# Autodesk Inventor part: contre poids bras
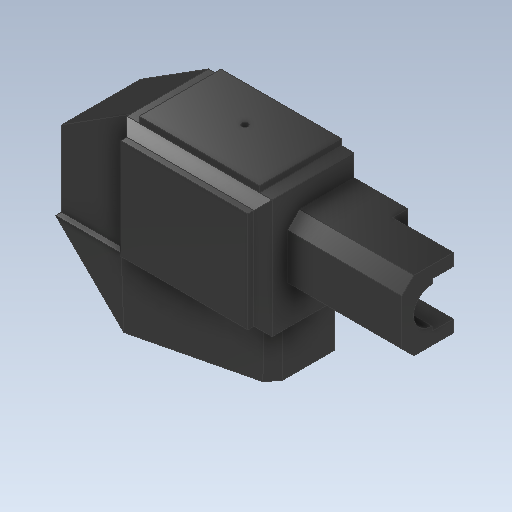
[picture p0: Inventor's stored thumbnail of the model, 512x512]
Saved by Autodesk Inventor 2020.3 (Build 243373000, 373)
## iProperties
Created: 2020-09
Part Number: contre poids bras
Material: Plastique ABS
Document SubType Name: Modeling
Designer: ficho
Density: 1.06 g/cm^3
Appearance: Lustré - Noir
Mass: 4.50875 g
Surface Area: 76.0656 cm^2
Volume: 4.25353 cm^3
Author: ficho
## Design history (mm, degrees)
sketch "Esquisse1"
  geometry: L1 (0, 0)-(146.6, 0); L2 (146.6, 0)-(146.6, -67.192); L3 (146.6, -67.192)-(0, -67.192); L4 (0, -67.192)-(0, 0); L5 (44.063, -33.051)-(55.308, -25.94); L6 (55.308, -25.94)-(79.294, -25.94); L7 (79.294, -25.94)-(79.294, -45.526); L8 (79.294, -45.526)-(76.04, -45.526); L9 (76.04, -45.526)-(76.04, -55.832); L10 (76.04, -55.832)-(55.308, -56.615); L11 (55.308, -56.615)-(44.063, -45.526); L12 (44.063, -45.526)-(44.063, -33.051); L13 (79.294, -29.495)-(98.206, -29.495); L14 (98.206, -29.495)-(98.206, -41.006); L15 (98.206, -41.006)-(79.294, -41.006); 2 further points; 1 other entity
  constraints: 22 end point, 5 perpendicular, 3 point on line, 2 horizontal, 1 parallel, 2 other
  dimensions: "d4" = 146.6 distance between parallel lines of L2 L4
  node "Image1"
extrude "Extrusion1" new body sketch "Esquisse1" distance "d6" = 15; taper "d7" = 0 deg
sketch "Esquisse2"
  geometry: L1 (79.294, -25.94)-(55.308, -25.94) reference; L2 (55.308, -25.94)-(55.308, -45.526); L3 (55.308, -45.526)-(43.978, -45.526); L4 (43.978, -45.526)-(43.978, -33.013); L5 (43.978, -33.013)-(55.308, -25.94); 1 further point
  constraints: 8 end point, 2 perpendicular, 1 vertical
extrude "Extrusion2" cut sketch "Esquisse2" distance "d8" = 2; taper "d9" = 0 deg
sketch "Esquisse3"
  geometry: L1 (55.308, -45.526)-(55.308, -56.615); L2 (44.063, -45.526)-(55.308, -56.615) reference; L3 (55.308, -56.615)-(44.063, -45.526); L4 (44.063, -45.526)-(55.308, -45.526); 1 further point
  constraints: 6 end point, 1 collinear, 1 perpendicular, 1 vertical
extrude "Extrusion3" cut sketch "Esquisse3" distance "d10" = 1; taper "d11" = 0 deg
sketch "Esquisse4"
  geometry: L1 (-20.746, 14)-(1.078, 9.792); L2 (0, 0)-(0, 15) reference; L3 (-20.746, 14)-(-20.746, 15); L4 (-20.746, 15)-(0, 15); L5 (4.381, 15)-(-19.588, 15) reference; L6 (0, 15)-(0, 10); L7 (0.389, 0)-(0.389, 15) reference; L8 (0, 15)-(1.078, 15); L9 (1.078, 15)-(1.078, 10); L10 (0, 10)-(0, 15); L11 (1.078, 10)-(1.078, 9.792); 3 further points
  constraints: 16 end point, 2 parallel, 2 point on line, 2 vertical, 1 coincident, 1 collinear, 1 horizontal, 1 perpendicular
extrude "Extrusion4" cut sketch "Esquisse4" stored distance "d13" = 10; taper "d14" = 0 deg
chamfer "Chanfrein1" distance "d16" = 1.5; stored, may be unused: second distance "d17" = 2, angle "d18" = 45 deg
sketch "Esquisse5"
  geometry: L1 (0, 15)-(18.912, 15) reference; L2 (0, 0)-(0, 15) reference; L3 (18.912, 15)-(0, 15); L4 (0, 15)-(0, 11); L5 (0, 11)-(18.912, 11); L6 (18.912, 11)-(18.912, 15); 1 further point
  constraints: 8 end point, 2 parallel, 1 horizontal, 1 perpendicular, 1 point on line
  dimensions: "d19" = 4 distance of L4.end L3.end
extrude "Extrusion5" cut sketch "Esquisse5" extent not by distance; stored distance "d20" = 15.609; taper "d21" = 0 deg
chamfer "Chanfrein2" distance "d22" = 1.5; stored, may be unused: second distance "d23" = 2, angle "d24" = 45 deg
sketch "Esquisse6"
  geometry: L1 (56.808, -44.026)-(56.808, -27.44) reference; L2 (77.794, -44.026)-(56.808, -44.026) reference; L3 (77.794, -27.44)-(77.794, -44.026) reference; L4 (56.808, -27.44)-(77.794, -27.44) reference; 1 further point
extrude "Extrusion6" join sketch "Esquisse6" distance "d25" = 1; taper "d26" = 0 deg
sketch "Esquisse7"
  geometry: L1 (23.986, -13.5)-(0, -13.5) reference; L2 (-55.308, 0)-(91.292, 0) reference; L3 (21.907, -13.5)-(21.907, 0); L4 (23.986, 0)-(0, 0) reference; L5 (2.045, -13.5)-(2.045, 0); L6 (21.907, -13.5)-(2.045, -13.5); L7 (2.045, 0)-(21.907, 0); 2 further points
  constraints: 8 end point, 4 point on line, 2 perpendicular, 1 collinear, 1 parallel
extrude "Extrusion7" join sketch "Esquisse7" distance "d27" = 1; taper "d28" = 0 deg
chamfer "Chanfrein3" distance "d29" = 2; stored, may be unused: second distance "d30" = 2, angle "d31" = 45 deg
sketch "Esquisse8"
  geometry: L1 (-11, 9.511)-(-11, 2) reference; L2 (0, 0)-(0, 11.511) reference; L3 (-6, 2.005)-(-2.5, 2.005); L4 (0, 2.005)-(0, 9.505); L5 (-2.5, 9.505)-(-6, 9.505); L6 (-2.5, -1.946)-(2.893, -1.946); L7 (2.893, -1.946)-(2.893, 18.713); L8 (2.893, 18.713)-(-2.5, 18.713); L9 (-6, 9.505)-(-6, 8.755); L10 (-6, 2.755)-(-6, 2.005); L11 (-2.5, 18.713)-(-2.5, 9.505); L12 (-2.5, 2.005)-(-2.5, -1.946); A1 r 3 centre (-6, 5.755) between (-6, 8.755) and (-6, 2.755); 1 further point
  constraints: 20 end point, 6 parallel, 2 horizontal, 2 perpendicular, 2 point on circle, 1 centre point, 1 point on line
  dimensions: "d32" = 6 diameter of A1; "d33" = 2 distance edge to line of A1 L1; "d34" = 3.75 distance from line of L3 A1.centre; "d35" = 3.75 distance from line of A1.centre L5 (= d34)
extrude "Extrusion8" cut sketch "Esquisse8" distance "d37" = 10; taper "d38" = 0 deg
sketch "Esquisse9"
  geometry: A1 r 3 centre (-6, 5.755) between (-6, 8.755) and (-6, 2.755) reference; 1 further point
hole "Perçage1" sketch "Esquisse9" at (-6, 5.755) diameter "d39" = 6; stored, may be unused: countersink angle "d43" = 90 deg, drill point angle "d45" = 118 deg; dims "d40" = 6, "d41" = 4, "d42" = 2, "d44" = 8
feature "Coque1" dims "d46" = 1
sketch "Esquisse10"
  geometry: L1 (-79.294, -25.94)-(-77.216, -25.94) reference; L2 (-76.04, -45.526)-(-79.294, -45.526) reference; L3 (-79.294, -25.94)-(-76.277, -25.94); L4 (-76.277, -25.94)-(-76.277, -45.526); L5 (-76.277, -45.526)-(-79.294, -45.526); L6 (-79.294, -45.526)-(-79.294, -25.94); 3 further points
  constraints: 8 end point, 2 parallel, 1 horizontal, 1 perpendicular, 1 point on line
extrude "Extrusion9" join sketch "Esquisse10" stored distance "d47" = 10; taper "d48" = 0 deg
sketch "Esquisse11"
  geometry: L1 (-79.294, -35.251)-(-97.206, -35.251) reference; 2 further points
  constraints: 1 point on line
hole "Perçage2" sketch "Esquisse11" at (-83.354, -35.251) diameter "d49" = 1.567; stored, may be unused: countersink angle "d53" = 90 deg, drill point angle "d55" = 118 deg; dims "d50" = 4, "d51" = 4, "d52" = 2, "d54" = 6.3
sketch "Esquisse12"
  geometry: L1 (-55.308, -45.526)-(-44.063, -45.526) reference; L2 (-44.651, -44.52)-(-44.651, -45.526); L3 (-75.333, -45.526)-(-75.333, -44.52); L4 (-57.485, -45.526)-(-79.294, -45.526) reference; L5 (-69.04, -45.526)-(-69.04, -44.52); L6 (-66.04, -45.526)-(-66.04, -44.52); L7 (-75.04, -54.869)-(-75.04, -44.526) reference; L8 (-44.651, -45.526)-(-66.04, -45.526); L9 (-69.04, -45.526)-(-75.333, -45.526); L10 (-75.333, -44.52)-(-69.04, -44.52); L11 (-66.04, -44.52)-(-44.651, -44.52); 3 further points
  constraints: 16 end point, 6 parallel, 4 perpendicular, 3 point on line, 2 horizontal
  dimensions: "d56" = 9 distance between parallel lines of L6 L7; "d57" = 6 distance between parallel lines of L5 L7
extrude "Extrusion10" join sketch "Esquisse12" stored distance "d58" = 10; taper "d59" = 0 deg
sketch "Esquisse14"
  geometry: L1 (23.986, 0)-(23.986, -13.5) reference; L2 (21.907, 0)-(2.045, 0) reference; 2 further points
  dimensions: "d60" = 12 distance from line of point (11.986, -6) L1; "d61" = 6 distance from line of point (11.986, -6) L2
hole "Perçage3" sketch "Esquisse14" at (11.986, -6) diameter "d62" = 1; stored, may be unused: countersink angle "d66" = 90 deg, drill point angle "d68" = 118 deg; dims "d63" = 4, "d64" = 4, "d65" = 2, "d67" = 6.3
node "Solide1"
node "Boucle projetée1"
other parameters: "d36" = 8.5
